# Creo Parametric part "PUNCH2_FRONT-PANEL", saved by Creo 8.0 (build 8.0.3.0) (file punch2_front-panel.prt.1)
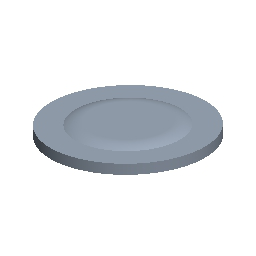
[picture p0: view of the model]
Units: millimeter Newton Second (mmNs); MM, TONNE, SECS

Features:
  1. datum plane "RIGHT"
  2. datum plane "TOP"
  3. datum plane "FRONT"
  4. coordinate system
  5. protrusion

Surfaces: 3 plane, 2 cylinder, 2 torus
